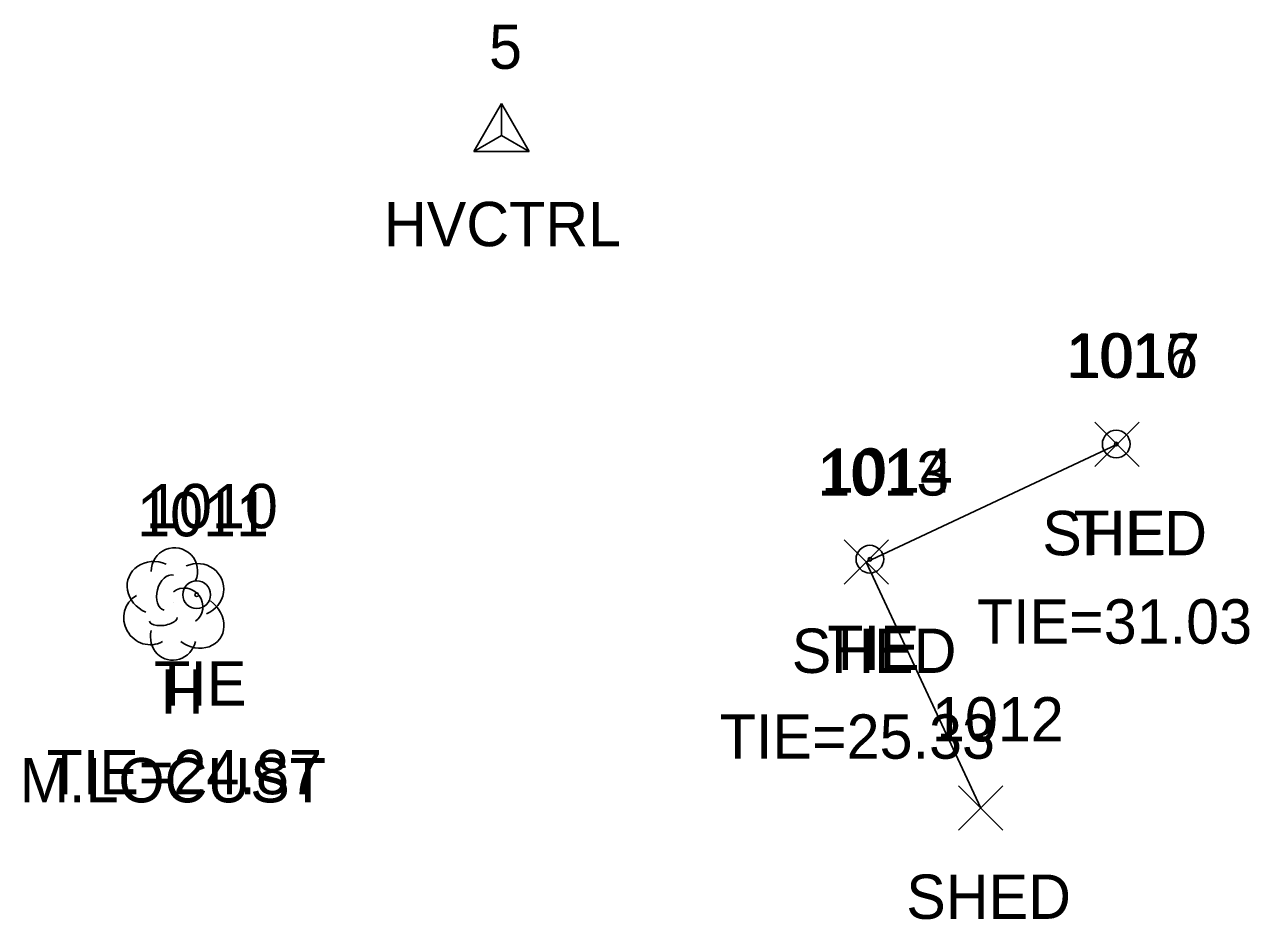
# Model space of a CAD drawing. Extents: x 1505684 to 1510253, y 730355 to 731397.
# Drawn here: x 1509624.7 to 1509680, y 730571.4 to 730611.8 of the extents above; entities that cross this region are included whole.
import ezdxf

# ---------------------------------------------------------------- set-up
doc = ezdxf.new("R2010")
doc.units = 0
for name, color, linetype in [('C_A', 7, 'Continuous'), ('C_C', 7, 'Continuous'), ('C_I', 7, 'Continuous'), ('CBP', 7, 'Continuous'), ('CPSM', 7, 'Continuous'), ('L_A', 7, 'Continuous'), ('L_C', 7, 'Continuous'), ('L_I', 7, 'Continuous'), ('L_TIC', 7, 'Continuous'), ('LBC', 7, 'Continuous'), ('LTD', 7, 'Continuous')]:
    doc.layers.add(name, color=color, linetype=linetype)

msp = doc.modelspace()

# ---------------------------------------------------------------- linework, layer by layer
at = {"layer": 'CBP'}
for centre, radius in [((1509673.994, 730592.838), 0.625), ((1509673.994, 730592.838), 0.0833), ((1509662.882, 730587.646), 0.625), ((1509662.882, 730587.646), 0.0833), ((1509632.516, 730586.042), 0.625), ((1509632.516, 730586.042), 0.0833)]:
    msp.add_circle(centre, radius, dxfattribs=at)
at = {"layer": 'CPSM'}
for p, q in [((1509645.018, 730606.041), (1509646.268, 730608.206)), ((1509647.518, 730606.041), (1509646.268, 730608.206)), ((1509646.268, 730606.762), (1509646.268, 730608.206)), ((1509645.018, 730606.041), (1509646.268, 730606.762)), ((1509646.268, 730606.762), (1509646.268, 730606.762)), ((1509646.268, 730606.762), (1509647.518, 730606.041)), ((1509645.018, 730606.041), (1509647.518, 730606.041))]:
    msp.add_line(p, q, dxfattribs=at)
at = {"layer": 'L_TIC'}
for points in [[(1509673.024, 730591.823), (1509675.024, 730593.823)], [(1509675.024, 730591.823), (1509673.024, 730593.823)], [(1509661.72, 730586.516), (1509663.72, 730588.516)], [(1509663.72, 730586.516), (1509661.72, 730588.516)], [(1509666.885, 730575.423), (1509668.885, 730577.423)], [(1509668.885, 730575.423), (1509666.885, 730577.423)]]:
    msp.add_lwpolyline(points, dxfattribs=at)
at = {"layer": 'LBC'}
msp.add_lwpolyline([(1509667.885, 730576.423), (1509662.72, 730587.516), (1509674.024, 730592.823)], dxfattribs=at)
at = {"layer": 'LTD'}
msp.add_line((1509631.464, 730585.677), (1509631.464, 730585.677), dxfattribs=at)
msp.add_line((1509631.464, 730585.677), (1509631.464, 730585.677), dxfattribs=at)
msp.add_arc((1509631.51, 730587.111), 1.047, 335.5272, 180.9563, dxfattribs=at)
for centre, major_axis, ratio, start_param, end_param in [((1509630.672, 730586.343), (1.21, -0.512), 0.895232, 1.570796, 4.712389), ((1509632.505, 730586.26), (-1.141, -0.483), 0.949671, 1.570796, 4.712389), ((1509631.255, 730586.135), (-0.208, -0.792), 0.645439, 3.141593, 6.283185), ((1509631.964, 730585.51), (-0.5, 0.667), 0.989748, 3.141593, 6.283185), ((1509630.38, 730584.968), (0.584, -1.042), 0.959034, 3.141593, 6.283185), ((1509632.464, 730584.843), (-1.09, 0.792), 0.841452, 1.570796, 4.712389), ((1509631.005, 730584.927), (-0.625, -0.083), 0.423636, 0, 3.141593), ((1509631.464, 730584.177), (0.265, 1.061), 0.942809, 1.570796, 4.712389)]:
    msp.add_ellipse(centre, major_axis=major_axis, ratio=ratio, start_param=start_param, end_param=end_param, dxfattribs=at)

# ---------------------------------------------------------------- texts
at = {"layer": 'C_A'}
for s, p in [('HVCTRL', (1509640.961, 730601.762)), ('TIE', (1509672.072, 730587.838)), ('TIE', (1509660.961, 730582.646)), ('TIE', (1509630.595, 730581.042))]:
    msp.add_text(s, height=2, dxfattribs=at).set_placement(p)
at = {"layer": 'C_C'}
for s, p in [('TIE=31.03', (1509667.71, 730583.838)), ('TIE=25.33', (1509656.11, 730578.646)), ('TIE=24.87', (1509625.745, 730577.042))]:
    msp.add_text(s, height=2, dxfattribs=at).set_placement(p)
at = {"layer": 'C_I'}
for s, p in [('5', (1509645.701, 730609.762)), ('1016', (1509671.734, 730595.838)), ('1014', (1509660.677, 730590.646)), ('1010', (1509630.225, 730589.042))]:
    msp.add_text(s, height=2, dxfattribs=at).set_placement(p)
at = {"layer": 'L_A'}
for s, p in [('SHED', (1509670.662, 730587.823)), ('SHED', (1509659.358, 730582.516)), ('H', (1509630.897, 730580.677)), ('SHED', (1509664.523, 730571.423))]:
    msp.add_text(s, height=2, dxfattribs=at).set_placement(p)
at = {"layer": 'L_C'}
msp.add_text('M.LOCUST', height=2, dxfattribs=at).set_placement((1509624.527, 730576.677))
at = {"layer": 'L_I'}
for s, p in [('1017', (1509671.82, 730595.823)), ('1013', (1509660.515, 730590.516)), ('1011', (1509629.826, 730588.677)), ('1012', (1509665.681, 730579.423))]:
    msp.add_text(s, height=2, dxfattribs=at).set_placement(p)

doc.saveas('drawing.dxf')
